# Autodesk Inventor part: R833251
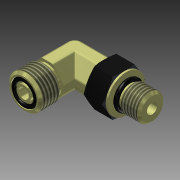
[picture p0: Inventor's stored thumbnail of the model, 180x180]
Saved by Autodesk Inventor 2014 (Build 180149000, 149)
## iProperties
Shininess: 20.0
Length Units: 11272
Angle Units: 11279
Time Units: 11290
Mass Units: 11286
Length Display Precision: 3
Angle Display Precision: 2
Company: Autodesk, Inc.
Created: 2002-05
Part Number: R833251
Material: Steel, Mild
Description: FITTING; EL-C9G4-S
Document SubType Name: Modeling
Designer: Autodesk, Inc.
Density: 8.182 g/cm^3
Appearance: Yellow Zinc
Density: 0.0
Volumn: 0.0
Area: 0.0
PropertySet Name: Model Information
Control State: 0
Master: False
Checked Out: False
Last Check In By: JT
Last Check In Date: 2003-06-20
Title: FITTING; EL-C9G4-S
Author: Autodesk, Inc.
Comments: -
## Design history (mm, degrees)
sketch "Sketch1"
  geometry: L1 (-7.144, 0)-(-7.144, 1.587); L2 (-7.144, 1.587)-(-2.381, 7.144); L3 (-2.381, 7.144)-(2.381, 7.144); L4 (2.381, 7.144)-(7.144, 1.587); L5 (7.144, 1.587)-(7.144, 0); L6 (-7.144, 0)-(0, 0); L7 (0, 0)-(7.144, 0); L8 (-7.144, -1.587)-(-7.144, 0); L9 (7.144, -1.587)-(7.144, 0); L10 (-7.144, -1.587)-(-2.381, -7.144); L11 (2.381, -7.144)-(7.144, -1.587); L12 (-2.381, -7.144)-(2.381, -7.144); C1 r 2.184 at (0, 0); 1 further point
  constraints: 24 end point, 4 equal length, 3 perpendicular, 2 horizontal, 2 vertical alignment, 1 centre point, 1 coincident, 1 collinear, 1 horizontal alignment
  dimensions: "d4" = 1.5875 distance of L1.start L1.end (= Flat_Spot); "d5" = 14.2875 distance between parallel lines of L5 L1 (= Wrench_Flats_JJ); "d6" = 4.7625 distance from line of L3.end L5 (= 3 x Flat_Spot); "d7" = 7.14375 distance from line of L3 point (0, 0) (= 0.5 x Wrench_Flats_JJ); "d8" = 4.7625 horizontal distance of L1.end L2.end (= 3 x Flat_Spot); "d9" = 7.14375 distance from line of L1 point (0, 0) (= 0.5 x d5); "d119" = 4.3688 diameter of C1 (derived)
extrude "Body Side 1" new body sketch "Sketch1" distance "d10" = 11.7856 (= M - CC); taper "d11" = 0 deg
sketch "Sketch2"
  geometry: L1 (0, -7.144)-(-1.587, -7.144); L2 (-1.587, -7.144)-(-7.144, -2.381); L3 (-7.144, -2.381)-(-7.144, 2.381); L4 (-7.144, 2.381)-(-1.587, 7.144); L5 (-1.587, 7.144)-(0, 7.144); L6 (0, -7.144)-(1.587, -7.144); L7 (1.587, -7.144)-(7.144, -2.381); L8 (7.144, -2.381)-(7.144, 2.381); L9 (7.144, 2.381)-(1.587, 7.144); L10 (1.587, 7.144)-(0, 7.144); L11 (0, -7.144)-(0, 0); L12 (0, 0)-(0, 7.144); C1 r 2.184 at (0, 0); 1 further point
  constraints: 24 end point, 5 equal length, 3 horizontal, 2 perpendicular, 1 centre point, 1 coincident, 1 collinear, 1 vertical, 1 vertical alignment
  dimensions: "d21" = 1.5875 distance of L1.start L1.end (= Flat_Spot); "d22" = 14.2875 distance between parallel lines of L5 L1 (= Wrench_Flats_JJ); "Flat_Spot_1" = 4.7625 vertical distance of L1.end L2.end (= 3 x Flat_Spot); "Flat_Spot_2" = 4.7625 vertical distance of L3.end L4.end (= 3 x Flat_Spot); "d25" = 7.14375 distance from line of L3 point (0, 0) (= 0.5 x Wrench_Flats_JJ); "d26" = 7.14375 distance from line of L1 point (0, 0) (= 0.5 x d22); "d120" = 4.3688 diameter of C1 (derived)
extrude "Body Side 2" join sketch "Sketch2" distance "d18" = 11.7856 (= M - CC); taper "d19" = 0 deg
sketch "Sketch3"
  geometry: L1 (0, 7.144)-(0, -7.144) reference; L2 (-2.381, 7.144)-(0, 7.144) reference; L3 (-7.144, 1.587)-(-2.381, 7.144) reference; L4 (-7.144, -1.587)-(-7.144, 1.587) reference; L5 (-2.381, -7.144)-(-7.144, -1.587) reference; L6 (0, -7.144)-(-2.381, -7.144) reference
revolve "Revolution1" sketch "Sketch3" stored, may be unused: angle "d27" = 90 deg
sketch "Sketch4"
  geometry: L1 (0, 0)-(0, 40.563); L2 (-2.184, 11.786)-(-6.134, 11.786); L3 (-6.134, 11.786)-(-6.134, 12.548); L4 (-6.134, 12.548)-(-7.144, 13.557); L5 (-7.144, 13.557)-(-7.144, 20.58); L6 (-7.144, 20.58)-(-6.134, 21.59); L7 (-6.134, 21.59)-(-5.499, 21.59); L8 (-5.499, 21.59)-(-5.499, 20.244); L9 (-5.499, 20.244)-(-3.086, 20.244); L10 (-3.086, 20.244)-(-3.086, 21.59); L11 (-3.086, 21.59)-(-2.184, 21.59); L12 (-2.184, 21.59)-(-2.184, 11.786); L13 (-6.134, 21.59)-(-6.134, 18.222)
  constraints: 26 end point, 5 perpendicular, 4 parallel, 2 collinear, 1 vertical
  dimensions: "d28" = 0.762 distance of L2.end L3.end (= Face_Seal_Undercut_Length_H); "d29" = 45 deg angle of L4 L5; "d30" = 9.8044 distance between parallel lines of L11 L2 (= CC); "d31" = 2.413 distance between parallel lines of L10 L8; "d32" = 4.3688 diameter of L12 L1 (= Face_Seal_ID); "d33" = 10.9982 diameter of L8 L1 (= Face_Seal_Groove_Dia); "d34" = 12.2682 diameter of L6.end L1 (= Face_Seal_Lip); "d35" = 14.2875 diameter of L5 L1 (= Face_Seal_Thread_OD); "d36" = 1.3462 distance between parallel lines of L7 L9; "d37" = 11.7856 distance from line of L2 L1.start (= M - CC)
revolve "Male Face-Seal" sketch "Sketch4" stored, may be unused: angle "d38" = 90 deg
feature "Male Face-Seal Thread" dims "d39" = 25.4, "d40" = 0
sketch "Sketch5"
  geometry: L1 (0, 0)-(0, 40.029); C1 r 0.794 at (-4.616, 21.038)
  constraints: 2 end point, 1 centre point, 1 vertical
  dimensions: "d41" = 1.5875 diameter of C1; "d42" = 21.03755 vertical distance of C1.centre L1.start (computed from M, d41); "d44" = 7.6454 dimension on C1 L1 (= Oring_Dia)
revolve "Male Face-Seal Oring" sketch "Sketch5" stored, may be unused: angle "d45" = 90 deg
fillet "Fillet1" dims "d80" = 1.524
sketch "Sketch10"
  geometry: L1 (0, 0)-(-36.602, 0); L2 (0, -2.184)-(0, -4.648); L3 (0, -4.648)-(-21.082, -4.648); L4 (-21.082, -7.938)-(-21.844, -7.938); L5 (-21.844, -7.938)-(-21.844, -4.648); L6 (-21.844, -4.648)-(-24.13, -4.648); L7 (-24.13, -4.648)-(-25.038, -5.556); L8 (-25.038, -5.556)-(-31.858, -5.556); L9 (-31.858, -5.556)-(-32.766, -4.648); L10 (-32.766, -4.648)-(-32.766, -2.184); L11 (-32.766, -2.184)-(0, -2.184); L12 (-21.082, -7.938)-(-21.082, -4.648)
  constraints: 24 end point, 5 parallel, 5 perpendicular, 2 collinear, 1 horizontal, 1 horizontal alignment, 1 vertical alignment
  dimensions: "T5" = 11.1125 diameter of L8 L1; "B1" = 15.875 diameter of L4.start L1; "D2" = 4.3688 diameter of L11 L1; "N2" = 32.766 distance from line of L10 L1.start; "XX" = 21.844 distance from line of L5 L1.start; "d88" = 45 deg angle of L8 L9; "Oring_Undercut_Length" = 2.286 distance of L5.end L6.end; "d95" = 0.762 distance of L4.start L4.end (= d28); "Oring_Undercut_Dia" = 9.2964 diameter of L6 L1
revolve "Male Oring" sketch "Sketch10" stored, may be unused: angle "d96" = 90 deg
sketch "Sketch13"
  geometry: L1 (-21.082, -2.978)-(-12.548, -2.978); L2 (-12.548, -2.978)-(-12.548, -7.938); L3 (-12.548, -7.938)-(-13.992, -11.906); L4 (-13.992, -11.906)-(-19.637, -11.906); L5 (-19.637, -11.906)-(-21.082, -7.938); L6 (-21.082, -7.938)-(-21.082, -2.978); L7 (0, 0)-(-44.107, 0)
  constraints: 14 end point, 3 perpendicular, 1 horizontal, 1 horizontal alignment, 1 parallel
  dimensions: "d111" = 21.082 distance from line of L6 L7.start (= XX - d28); "d112" = 70 deg angle of L4 L5; "d113" = 70 deg angle of L4 L3; "d114" = 15.875 diameter of L5.end L7 (= B1); "d115" = 12.5476 distance from line of L2 L7.start (= -CC + M + d28); "d116" = 5.9563 diameter of L1 L7 (computed from D2); "d117" = 23.8125 diameter of L4 L7 (= 1.5 x B1)
revolve "Nut" sketch "Sketch13" stored, may be unused: angle "d118" = 90 deg
sketch "Sketch11"
  geometry: L1 (4.583, 7.938)-(9.165, 0); L2 (9.165, 0)-(4.583, -7.938); L3 (4.583, -7.938)-(-4.583, -7.938); L4 (-4.583, -7.938)-(-9.165, 0); L5 (-9.165, 0)-(-4.583, 7.938); L6 (-4.583, 7.938)-(4.583, 7.938); C1 r 7.937 at (0, 0) reference; C2 r 15.875 at (0, 0); 1 further point
  constraints: 12 end point, 2 coincident, 1 centre point, 1 horizontal, 11 other
  dimensions: "d98" = 15.875 distance between parallel lines of L3 L6 (= B1); "d99" = 31.75 diameter of C2 (= 2 x B1)
extrude "Nut2" cut sketch "Sketch11" stored distance "d100" = 25.4; taper "d101" = 0 deg
sketch "Sketch12"
  geometry: L1 (4.735, 0)-(-28.407, 0) reference; C1 r 0.914 at (-22.758, 5.124); 1 further point
  constraints: 1 centre point
  dimensions: "d104" = 5.12445 vertical distance of point (0, 0) C1.centre (= -d36 + 0.5 x T5 + 0.5 x ORING_DIA); "d105" = 22.7584 horizontal distance of point (0, 0) C1.centre (= XX + 0.5 x ORING_DIA); "ORING_DIA" = 1.8288 diameter of C1
revolve "Male Oring-Oring" sketch "Sketch12" stored, may be unused: angle "d109" = 90 deg
feature "Male Oring-Thread" dims "d102" = 25.4, "d103" = 0
body "Solid1"
other parameters: "CC" = 9.8044 [user parameter; used in 5 equation terms], "Face_Seal_Undercut_Length_H" = 0.762 [user parameter; used in 1 equation term], "Face_Seal_ID" = 4.3688 [user parameter; used in 1 equation term], "Face_Seal_Groove_Dia" = 10.9982 [user parameter; used in 1 equation term], "Face_Seal_Lip" = 12.2682 [user parameter; used in 1 equation term], "Face_Seal_Thread_OD" = 14.2875 [user parameter; used in 1 equation term], "Wrench_Flats_JJ" = 14.2875 [user parameter; used in 4 equation terms], "Flat_Spot" = 1.5875 [user parameter; used in 6 equation terms], "M" = 21.59 [user parameter; used in 5 equation terms], "Oring_Dia" = 7.6454 [user parameter; used in 1 equation term]
